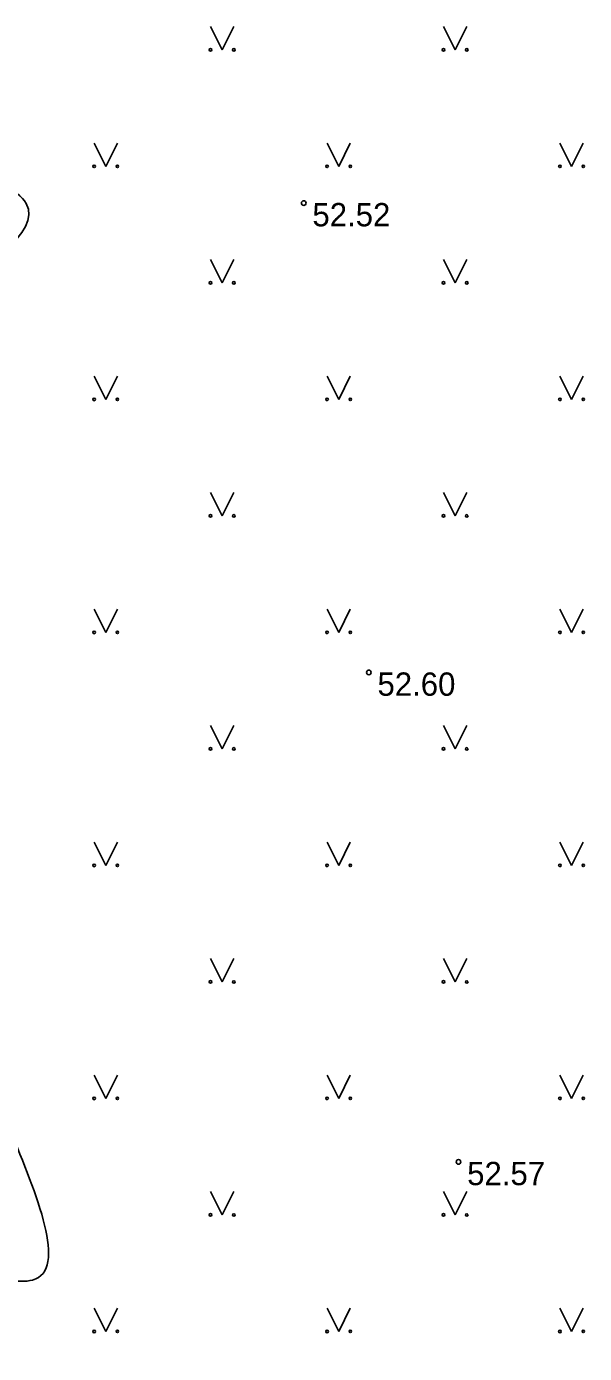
# Model space of a CAD drawing. Extents: x 619806 to 620082, y 405176 to 405386.
# Drawn here: x 619920.8 to 619932.78, y 405297.03 to 405325.5 of the extents above; entities that cross this region are included whole.
import ezdxf

# ---------------------------------------------------------------- set-up
doc = ezdxf.new("R2010")
doc.units = 0
for name, color, linetype in [('RELJ_AATZ_####_TKST_#', 7, 'Continuous'), ('RELJ_ELEM_####_####_#', 7, 'Continuous'), ('RELJ_HORZ_PAMT_####_#', 7, 'Continuous'), ('TERT_ELEM_####_####_#', 7, 'Continuous')]:
    doc.layers.add(name, color=color, linetype=linetype)

msp = doc.modelspace()

# ---------------------------------------------------------------- linework, layer by layer
at = {"layer": 'RELJ_ELEM_####_####_#'}
for centre in [(619926.75, 405321.713), (619928.147, 405311.64), (619930.072, 405301.138)]:
    msp.add_circle(centre, 0.05, dxfattribs=at)
at = {"layer": 'RELJ_HORZ_PAMT_####_#'}
msp.add_spline([(619907.956, 405308.464), (619910.402, 405307.562), (619913.86, 405304.951), (619915.602, 405304.09), (619915.602, 405305.597), (619912.968, 405313.592), (619912.89, 405315.511), (619914.687, 405318.349), (619915.7, 405320.324), (619916.9, 405321.328), (619919.524, 405322.347), (619920.794, 405321.7), (619918.865, 405319.529), (619916.618, 405315.954), (619917.647, 405309.917), (619920.445, 405301.831), (619920.93, 405298.602), (619919.742, 405298.823), (619918.41, 405299.521), (619915.057, 405297.864), (619909.729, 405295.803), (619908.377, 405296.58), (619903.524, 405293.78), (619899.119, 405293.642)], degree=3, dxfattribs=at)
at = {"layer": 'TERT_ELEM_####_####_#'}
for p, q in [((619924.75, 405325.5), (619925, 405325)), ((619925, 405325), (619925.25, 405325.5)), ((619929.75, 405325.5), (619930, 405325)), ((619930, 405325), (619930.25, 405325.5)), ((619922.25, 405323), (619922.5, 405322.5)), ((619922.5, 405322.5), (619922.75, 405323)), ((619927.25, 405323), (619927.5, 405322.5)), ((619927.5, 405322.5), (619927.75, 405323)), ((619932.25, 405323), (619932.5, 405322.5)), ((619932.5, 405322.5), (619932.75, 405323)), ((619924.75, 405320.5), (619925, 405320)), ((619925, 405320), (619925.25, 405320.5)), ((619929.75, 405320.5), (619930, 405320)), ((619930, 405320), (619930.25, 405320.5)), ((619922.25, 405318), (619922.5, 405317.5)), ((619922.5, 405317.5), (619922.75, 405318)), ((619927.25, 405318), (619927.5, 405317.5)), ((619927.5, 405317.5), (619927.75, 405318)), ((619932.25, 405318), (619932.5, 405317.5)), ((619932.5, 405317.5), (619932.75, 405318)), ((619924.75, 405315.5), (619925, 405315)), ((619925, 405315), (619925.25, 405315.5)), ((619929.75, 405315.5), (619930, 405315)), ((619930, 405315), (619930.25, 405315.5)), ((619922.25, 405313), (619922.5, 405312.5)), ((619922.5, 405312.5), (619922.75, 405313)), ((619927.25, 405313), (619927.5, 405312.5)), ((619927.5, 405312.5), (619927.75, 405313)), ((619932.25, 405313), (619932.5, 405312.5)), ((619932.5, 405312.5), (619932.75, 405313)), ((619924.75, 405310.5), (619925, 405310)), ((619925, 405310), (619925.25, 405310.5)), ((619929.75, 405310.5), (619930, 405310)), ((619930, 405310), (619930.25, 405310.5)), ((619922.25, 405308), (619922.5, 405307.5)), ((619922.5, 405307.5), (619922.75, 405308)), ((619927.25, 405308), (619927.5, 405307.5)), ((619927.5, 405307.5), (619927.75, 405308)), ((619932.25, 405308), (619932.5, 405307.5)), ((619932.5, 405307.5), (619932.75, 405308)), ((619924.75, 405305.5), (619925, 405305)), ((619925, 405305), (619925.25, 405305.5)), ((619929.75, 405305.5), (619930, 405305)), ((619930, 405305), (619930.25, 405305.5)), ((619922.25, 405303), (619922.5, 405302.5)), ((619922.5, 405302.5), (619922.75, 405303)), ((619927.25, 405303), (619927.5, 405302.5)), ((619927.5, 405302.5), (619927.75, 405303)), ((619932.25, 405303), (619932.5, 405302.5)), ((619932.5, 405302.5), (619932.75, 405303)), ((619924.75, 405300.5), (619925, 405300)), ((619925, 405300), (619925.25, 405300.5)), ((619929.75, 405300.5), (619930, 405300)), ((619930, 405300), (619930.25, 405300.5)), ((619922.25, 405298), (619922.5, 405297.5)), ((619922.5, 405297.5), (619922.75, 405298)), ((619927.25, 405298), (619927.5, 405297.5)), ((619927.5, 405297.5), (619927.75, 405298)), ((619932.25, 405298), (619932.5, 405297.5)), ((619932.5, 405297.5), (619932.75, 405298))]:
    msp.add_line(p, q, dxfattribs=at)
for centre, radius in [((619924.75, 405325), 0.028), ((619925.25, 405325), 0.0263), ((619929.75, 405325), 0.028), ((619930.25, 405325), 0.0263), ((619922.25, 405322.5), 0.028), ((619922.75, 405322.5), 0.0263), ((619927.25, 405322.5), 0.028), ((619927.75, 405322.5), 0.0263), ((619932.25, 405322.5), 0.028), ((619932.75, 405322.5), 0.0263), ((619924.75, 405320), 0.028), ((619925.25, 405320), 0.0263), ((619929.75, 405320), 0.028), ((619930.25, 405320), 0.0263), ((619922.25, 405317.5), 0.028), ((619922.75, 405317.5), 0.0263), ((619927.25, 405317.5), 0.028), ((619927.75, 405317.5), 0.0263), ((619932.25, 405317.5), 0.028), ((619932.75, 405317.5), 0.0263), ((619924.75, 405315), 0.028), ((619925.25, 405315), 0.0263), ((619929.75, 405315), 0.028), ((619930.25, 405315), 0.0263), ((619922.25, 405312.5), 0.028), ((619922.75, 405312.5), 0.0263), ((619927.25, 405312.5), 0.028), ((619927.75, 405312.5), 0.0263), ((619932.25, 405312.5), 0.028), ((619932.75, 405312.5), 0.0263), ((619924.75, 405310), 0.028), ((619925.25, 405310), 0.0263), ((619929.75, 405310), 0.028), ((619930.25, 405310), 0.0263), ((619922.25, 405307.5), 0.028), ((619922.75, 405307.5), 0.0263), ((619927.25, 405307.5), 0.028), ((619927.75, 405307.5), 0.0263), ((619932.25, 405307.5), 0.028), ((619932.75, 405307.5), 0.0263), ((619924.75, 405305), 0.028), ((619925.25, 405305), 0.0263), ((619929.75, 405305), 0.028), ((619930.25, 405305), 0.0263), ((619922.25, 405302.5), 0.028), ((619922.75, 405302.5), 0.0263), ((619927.25, 405302.5), 0.028), ((619927.75, 405302.5), 0.0263), ((619932.25, 405302.5), 0.028), ((619932.75, 405302.5), 0.0263), ((619924.75, 405300), 0.028), ((619925.25, 405300), 0.0263), ((619929.75, 405300), 0.028), ((619930.25, 405300), 0.0263), ((619922.25, 405297.5), 0.028), ((619922.75, 405297.5), 0.0263), ((619927.25, 405297.5), 0.028), ((619927.75, 405297.5), 0.0263), ((619932.25, 405297.5), 0.028), ((619932.75, 405297.5), 0.0263)]:
    msp.add_circle(centre, radius, dxfattribs=at)

# ---------------------------------------------------------------- texts
at = {"layer": 'RELJ_AATZ_####_TKST_#'}
for s, p in [(' 52.52', (619926.75, 405321.213)), (' 52.60', (619928.147, 405311.14)), (' 52.57', (619930.072, 405300.638))]:
    msp.add_text(s, height=0.5, dxfattribs=at).set_placement(p)

doc.saveas('drawing.dxf')
